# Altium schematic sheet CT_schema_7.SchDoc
size 411 x 402 mm
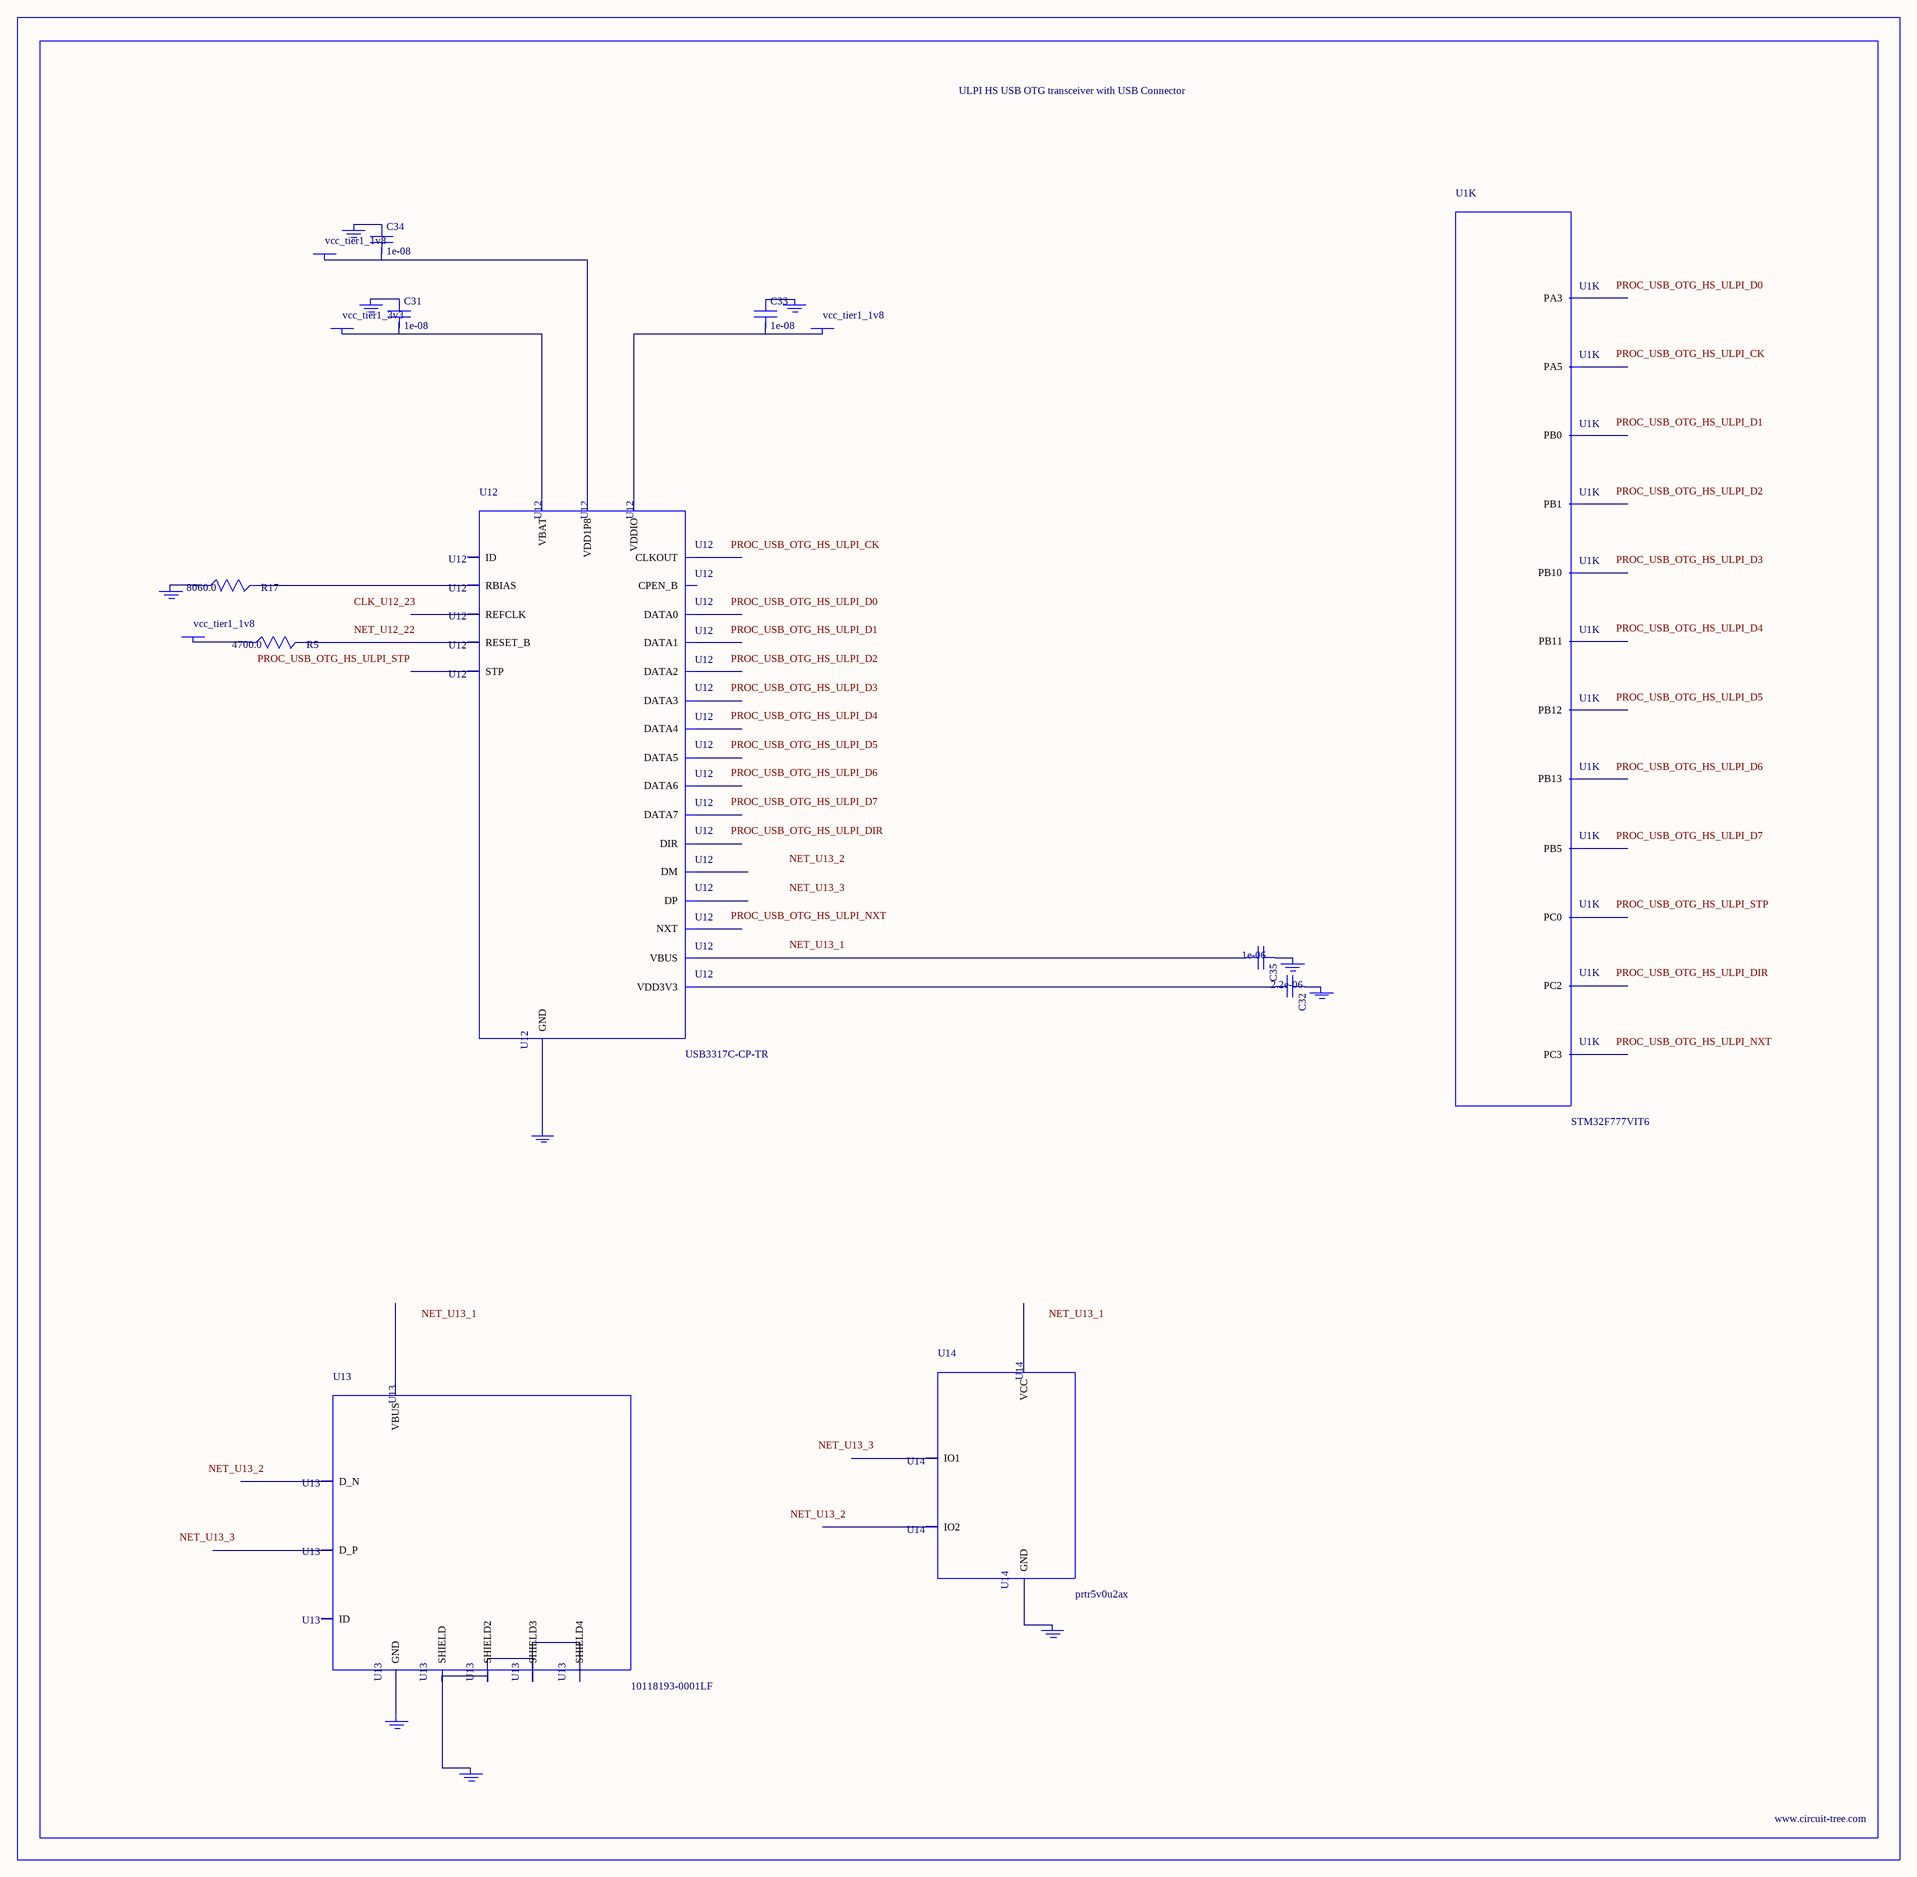
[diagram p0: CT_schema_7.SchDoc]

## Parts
BORDER6  (no value)
C31  1e-08  [C0402]
C32  2.2e-06  [C0603]
C33  1e-08  [C0402]
C34  1e-08  [C0402]
C35  1e-06  [C0603]
GND_INSTANCE_6_0  (no value)
GND_INSTANCE_6_1  (no value)
GND_INSTANCE_6_2  (no value)
GND_INSTANCE_6_3  (no value)
GND_INSTANCE_6_4  (no value)
GND_INSTANCE_6_5  (no value)
GND_INSTANCE_6_6  (no value)
GND_INSTANCE_6_7  (no value)
GND_INSTANCE_6_8  (no value)
GND_INSTANCE_6_9  (no value)
POWER_INSTANCE_6_0  vcc_tier1_3v3
POWER_INSTANCE_6_1  vcc_tier1_1v8
POWER_INSTANCE_6_2  vcc_tier1_1v8
POWER_INSTANCE_6_3  vcc_tier1_1v8
R5  4700.0  [R0603]
R17  8060.0  [R0603]
U1  STM32F777VIT6  [LQFP100]  (part K of 11)
U12  USB3317C-CP-TR  [QFN-24]
U13  10118193-0001LF  [FCI_10118193-0001LF]
U14  prtr5v0u2ax  [SOT143B]

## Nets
NetC31_1: C31.1 GND_INSTANCE_6_1.0(GND)
NetC31_2: C31.2 POWER_INSTANCE_6_0.0(PWR) U12.3(VBAT)
NetC32_1: C32.1 GND_INSTANCE_6_2.0(GND)
NetC32_2: C32.2 U12.4(VDD3V3)
NetC33_1: C33.1 GND_INSTANCE_6_3.0(GND)
NetC33_2: C33.2 POWER_INSTANCE_6_1.0(PWR) U12.17(VDDIO)
NetC34_1: C34.1 GND_INSTANCE_6_4.0(GND)
NetC34_2: C34.2 POWER_INSTANCE_6_2.0(PWR) U12.21(VDD1P8)
NetC35_1: C35.1 GND_INSTANCE_6_0.0(GND)
NetC35_2: C35.2 U12.2(VBUS)
NetGND_INSTANCE_6_5_0: GND_INSTANCE_6_5.0(GND) R17.1
NetGND_INSTANCE_6_6_0: GND_INSTANCE_6_6.0(GND) U12.25(GND)
NetGND_INSTANCE_6_7_0: GND_INSTANCE_6_7.0(GND) U13.6(SHIELD) U13.7(SHIELD2) U13.8(SHIELD3) U13.9(SHIELD4)
NetGND_INSTANCE_6_8_0: GND_INSTANCE_6_8.0(GND) U13.5(GND)
NetGND_INSTANCE_6_9_0: GND_INSTANCE_6_9.0(GND) U14.1(GND)
NetPOWER_INSTANCE_6_3_0: POWER_INSTANCE_6_3.0(PWR) R5.1
NetR5_2: R5.2 U12.22(RESET_B)
NetR17_2: R17.2 U12.24(RBIAS)

Not connected (* = marked no-connect by the designer): U1 15(PC0) 17(PC2) 18(PC3) 25(PA3) 29(PA5) 34(PB0) 35(PB1) 46(PB10) 47(PB11) 51(PB12) 52(PB13) 91(PB5); U12 1(ID) 5(DM) 6(DP) 7(CPEN_B) 8(DATA7) 9(DATA6) 10(DATA5) 11(DATA4) 12(CLKOUT) 13(DATA3) 14(DATA2) 15(DATA1) 16(DATA0) 18(NXT) 19(DIR) 20(STP) 23(REFCLK); U13 1(VBUS) 2(D_N) 3(D_P) 4(ID); U14 2(IO1) 3(IO2) 4(VCC)

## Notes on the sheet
- Labels drawn without touching a wire or pin: CLK_U12_23, NET_U12_22, NET_U13_1, NET_U13_2, NET_U13_3, PROC_USB_OTG_HS_ULPI_CK, PROC_USB_OTG_HS_ULPI_D0, PROC_USB_OTG_HS_ULPI_D1, PROC_USB_OTG_HS_ULPI_D2, PROC_USB_OTG_HS_ULPI_D3, PROC_USB_OTG_HS_ULPI_D4, PROC_USB_OTG_HS_ULPI_D5, PROC_USB_OTG_HS_ULPI_D6, PROC_USB_OTG_HS_ULPI_D7, PROC_USB_OTG_HS_ULPI_DIR, PROC_USB_OTG_HS_ULPI_NXT, PROC_USB_OTG_HS_ULPI_STP

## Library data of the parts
BORDER6 = BORDER_PAGE6
C31 C33 C34 = C0402C103K3RAC
C32 = C0603C225K8RACTU
C35 = C0603C105K3RACTU
GND_INSTANCE_6_0-GND_INSTANCE_6_9 = GND
POWER_INSTANCE_6_0-POWER_INSTANCE_6_3 = PWR
R5 = RC0603JR-074K7L
R17 = ERJ-3EKF8061V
